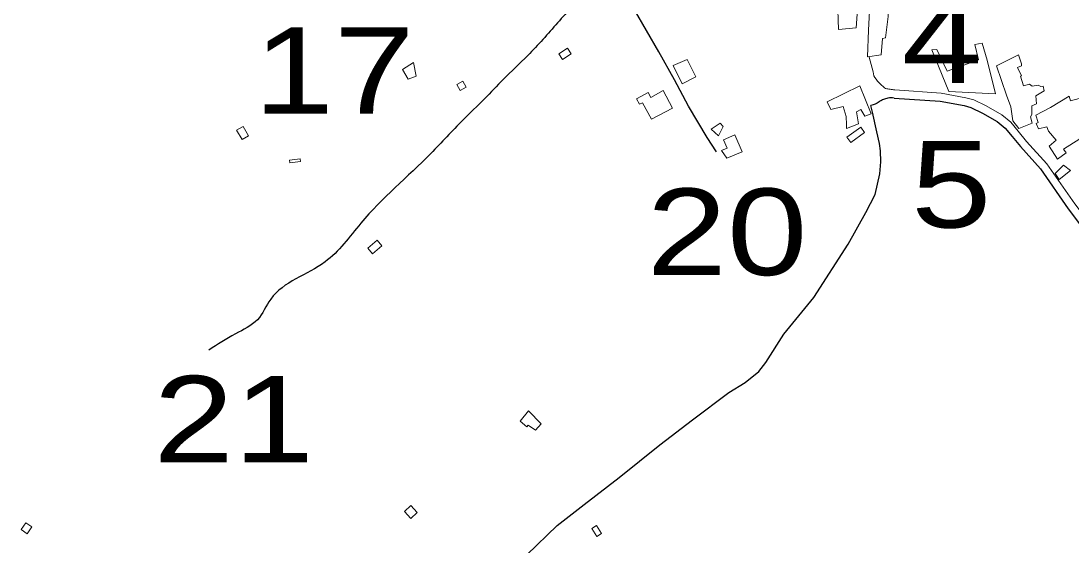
# Model space of a CAD drawing. Extents: x 476989 to 498418, y 4381813 to 4416555.
# Drawn here: x 485637 to 486244, y 4385659 to 4385963 of the extents above; entities that cross this region are included whole.
import ezdxf
from ezdxf.enums import TextEntityAlignment as Align

# ---------------------------------------------------------------- set-up
doc = ezdxf.new("R2010")
doc.units = 0
doc.header["$LTSCALE"] = 20
for name, color, linetype, lineweight in [('13', 7, 'Continuous', 13), ('36', 7, 'Continuous', 13), ('37', 7, 'Continuous', 13), ('47', 7, 'Continuous', 13), ('6', 7, 'Continuous', 25)]:
    doc.layers.add(name, color=color, linetype=linetype, lineweight=lineweight)

msp = doc.modelspace()

# ---------------------------------------------------------------- linework, layer by layer
at = {"layer": '36'}
msp.add_lwpolyline([(486142.37, 4385922.73), (486169.25, 4385920.92), (486183.49, 4385918.24), (486188.02, 4385917.05), (486195.24, 4385913.48), (486204.23, 4385908.31), (486209.48, 4385904.02), (486213.82, 4385898.89), (486218.57, 4385893.02), (486230.28, 4385879.98), (486246.4, 4385856.86), (486269.75, 4385825.93), (486300.13, 4385786.91), (486328.91, 4385748), (486353.38, 4385716.35), (486380.75, 4385678.67), (486392.21, 4385664.02)], dxfattribs=at)
msp.add_spline([(486142.37, 4385922.73), (486139.75, 4385923.12), (486137.13, 4385923.61), (486134.98, 4385925.29), (486133.35, 4385926.89), (486130.24, 4385930.96)], degree=3, dxfattribs=at)
at = {"layer": '37'}
msp.add_lwpolyline([(486130.24, 4385930.95), (486129.88, 4385933.25), (486127.56, 4385941.69)], dxfattribs=at)
at = {"layer": '47'}
for points in [[(486126.74, 4385941.77), (486127.18, 4385957.29), (486128.4, 4385979.26), (486128.74, 4385992.54), (486130.59, 4386006.69), (486132.4, 4386012.14), (486136.31, 4386023.42), (486141.41, 4386023.42), (486140.94, 4386021.55), (486146.07, 4386018.4), (486144.28, 4386009.05), (486142.12, 4385999.7), (486138.15, 4385999.83), (486137.96, 4385986.4), (486138.64, 4385976.56), (486138.63, 4385965.08), (486137.1, 4385952.8), (486135.29, 4385952.45), (486134.48, 4385942.93)], [(486121.21, 4385974.86), (486120.15, 4385958.52), (486109.86, 4385957.61), (486109.27, 4385974.66)], [(486200.64, 4385920.52), (486173.65, 4385921.81), (486163.79, 4385945.89), (486166.72, 4385946.14), (486172.62, 4385933.53), (486190.79, 4385940.17), (486188.67, 4385948.98), (486192.96, 4385949.67), (486195.89, 4385939.95)], [(485948.25, 4385943.57), (485953.22, 4385946.83), (485955.38, 4385943.55), (485950.41, 4385940.29)], [(486201.25, 4385936.57), (486213.87, 4385942.92), (486215.6, 4385937.86), (486215.73, 4385936.66), (486213.39, 4385935.72), (486215.72, 4385930.81), (486215.04, 4385930.67), (486216.76, 4385925.02), (486220.38, 4385926.02), (486221.87, 4385924.94), (486225.33, 4385925.49), (486226.74, 4385924.72), (486228.09, 4385924.85), (486228.81, 4385922.22), (486223.89, 4385919.36), (486224.35, 4385914.78), (486221.55, 4385913.47), (486221.63, 4385908.51), (486220.93, 4385907.1), (486221.78, 4385903.48), (486214.09, 4385900.52), (486210.7, 4385904.92), (486209.46, 4385913.04), (486207.08, 4385919.68)], [(485861.23, 4385928.92), (485857.93, 4385934.52), (485864.29, 4385938.63), (485865.76, 4385930.65)], [(486022.34, 4385940.26), (486027.38, 4385930.21), (486019.57, 4385926.31), (486014.29, 4385936.87)], [(485892.73, 4385927.86), (485894.72, 4385924.36), (485891.3, 4385922.41), (485889.31, 4385925.91)], [(486128.74, 4385908.95), (486122.3, 4385925.1), (486103.41, 4385915.91), (486105.37, 4385911.38), (486112.59, 4385913.08), (486114.31, 4385907.35), (486114.47, 4385902.7), (486114.44, 4385900.52), (486121.38, 4385903.12), (486120.36, 4385910.12), (486122.85, 4385911.43), (486125.05, 4385907.5)], [(486001.74, 4385905.82), (485996.55, 4385915.34), (485994.89, 4385914.44), (485993.22, 4385917.49), (485999.91, 4385921.16), (486001.4, 4385918.43), (486008.48, 4385922.31), (486014.01, 4385912.2)], [(486265.73, 4385922.59), (486251.79, 4385918.59), (486244.03, 4385916.37), (486243.24, 4385919.16), (486232.42, 4385912.64), (486224.03, 4385908.18), (486225.24, 4385903.96), (486224.11, 4385903.38), (486225.41, 4385900.28), (486230.23, 4385901.41), (486231.25, 4385898.92), (486235.75, 4385893.61), (486231.72, 4385890.14), (486236.49, 4385882.79), (486241.42, 4385886.4), (486239.95, 4385888.52), (486263.96, 4385903.63), (486258.32, 4385913.84), (486263.67, 4385915.19), (486268.6, 4385908.14), (486273.16, 4385912.43)], [(485762.06, 4385899.5), (485765.2, 4385894.06), (485768.99, 4385896.25), (485765.85, 4385901.69)], [(486040.62, 4385896.25), (486043.32, 4385901.69), (486041.48, 4385903.59), (486036.32, 4385900.14)], [(486114.74, 4385895.34), (486122.72, 4385901.13), (486124.91, 4385898.12), (486116.93, 4385892.33)], [(486045.39, 4385883.2), (486054.22, 4385886.98), (486050.02, 4385896.78), (486043.46, 4385893.98), (486045.53, 4385889.1), (486042.2, 4385887.69)], [(485798.94, 4385881.34), (485792.79, 4385880.56), (485792.58, 4385882.18), (485798.73, 4385882.96)], [(486239.89, 4385879.21), (486235.17, 4385874.48), (486237.52, 4385870.92), (486244.05, 4385876.23)], [(485843.31, 4385835.83), (485846.04, 4385832.55), (485840.57, 4385827.99), (485837.84, 4385831.27)], [(485930.74, 4385737.25), (485937.99, 4385729.79), (485934.78, 4385726.16), (485930.62, 4385729), (485929.71, 4385728.11), (485925.93, 4385731.31)], [(485862.8, 4385682.54), (485859.04, 4385679.07), (485862.69, 4385675.12), (485866.45, 4385678.59)], [(485640.17, 4385672.6), (485643.66, 4385670.19), (485640.91, 4385666.22), (485637.42, 4385668.63)], [(485967.28, 4385669.27), (485970.22, 4385664.72), (485972.94, 4385666.48), (485970, 4385671.03)]]:
    msp.add_lwpolyline(points, close=True, dxfattribs=at)
at = {"layer": '6'}
for points in [[(486039.35, 4385887.02), (486034.01, 4385895.17), (486023.27, 4385913.43), (486015.17, 4385928.47), (486006.09, 4385944.75), (485991.82, 4385969.4), (485979.85, 4385992.89), (485968.11, 4386013.21), (485958.85, 4386029.11)], [(486142.05, 4385918.05), (486168.65, 4385916.25), (486182.46, 4385913.66), (486186.37, 4385912.63), (486193.03, 4385909.34), (486201.55, 4385904.44), (486206.17, 4385900.66), (486210.21, 4385895.9), (486215, 4385889.97), (486226.59, 4385877.06), (486242.6, 4385854.11), (486266.03, 4385823.08), (486296.39, 4385784.07), (486326.62, 4385746.3), (486351.18, 4385714.3), (486378.4, 4385677.31), (486393.42, 4385659.22)], [(485929.7, 4385654.12), (485947.21, 4385671), (485962.86, 4385683.17), (485983.11, 4385698.85), (486006.57, 4385717.65), (486025.47, 4385732.16), (486046.49, 4385747.94), (486055.86, 4385753.58), (486063.86, 4385760.09), (486067.88, 4385765.26), (486078.26, 4385781.54), (486095.66, 4385802.83), (486115.53, 4385833.66), (486125.62, 4385851.88), (486131, 4385862.35), (486133.77, 4385874.18), (486134.33, 4385881.18), (486134.19, 4385887.6), (486133.51, 4385891.85), (486132.03, 4385898.54), (486129.5, 4385909.84), (486128.5, 4385913.78)]]:
    msp.add_lwpolyline(points, dxfattribs=at)
for points in [[(485956.23, 4385971.26), (485947.54, 4385961.52), (485930.31, 4385942.56), (485916.08, 4385928.8), (485905.26, 4385917.55), (485892.78, 4385905.28), (485874.27, 4385886.03), (485833.81, 4385845.65), (485813.14, 4385823.32), (485781.72, 4385801.83), (485774.07, 4385789.96), (485761.33, 4385781.76), (485746.04, 4385772.43)], [(486142.05, 4385918.05), (486138.4, 4385917.96), (486135.84, 4385917.17), (486134.71, 4385916.66), (486134.13, 4385916.37), (486133.53, 4385915.97), (486133.32, 4385915.78), (486128.56, 4385913.68)]]:
    msp.add_spline(points, degree=3, dxfattribs=at)

# ---------------------------------------------------------------- texts
at = {"layer": '13', "width": 1.25}
for s, p in [('4', (486169.71, 4385926.78)), ('17', (485818.36, 4385908.92)), ('5', (486175.03, 4385843.18)), ('20', (486045.47, 4385815.74)), ('21', (485760.4, 4385707.46))]:
    msp.add_text(s, height=50, dxfattribs=at).set_placement(p, align=Align.CENTER)

doc.saveas('drawing.dxf')
